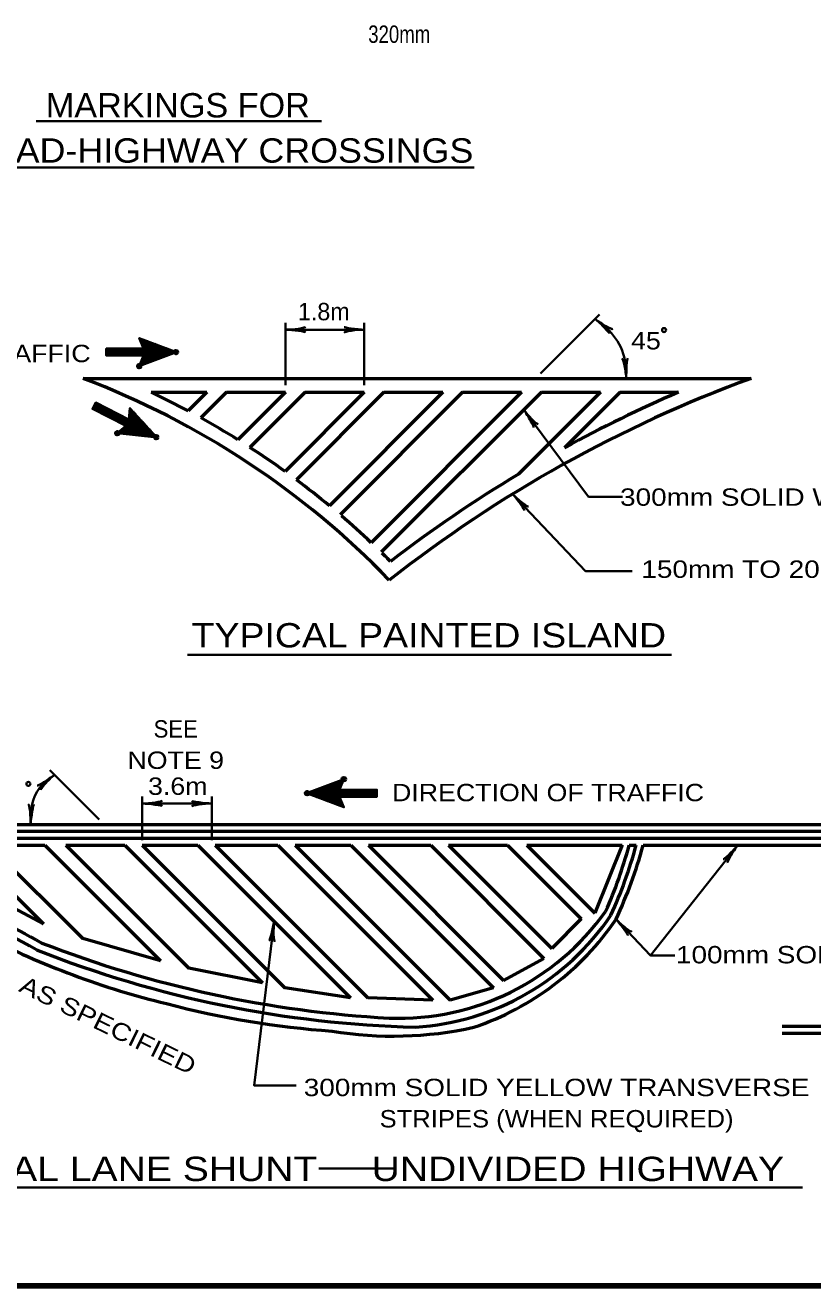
# Model space of a CAD drawing. Extents: x -96 to 617, y -65 to 388.
# Drawn here: x 24.1 to 137.3, y -55.4 to 125.9 of the extents above; entities that cross this region are included whole.
import ezdxf
from ezdxf.enums import TextEntityAlignment as Align

# ---------------------------------------------------------------- set-up
doc = ezdxf.new("R2010")
doc.units = 0
doc.header["$PDMODE"] = 32
doc.header["$PDSIZE"] = 0.5
doc.layers.add('1', color=7, linetype='Continuous', lineweight=53)

msp = doc.modelspace()

# ---------------------------------------------------------------- linework, layer by layer
at = {"layer": '1', "lineweight": 40}
for p, q in [((25.644, 112.056), (66.627, 112.056)), ((3.249, 105.393), (88.592, 105.393)), ((47.366, 35.304), (116.953, 35.304)), ((66.278, -38.548), (77.278, -38.548)), ((3.977, -41.268), (135.772, -41.268))]:
    msp.add_line(p, q, dxfattribs=at)
at = {"layer": '1', "lineweight": 35}
for p, q in [((106.608, 84.265), (98.123, 75.78)), ((61.474, 74.073), (61.474, 83.073)), ((61.474, 82.073), (72.788, 82.073)), ((72.788, 74.073), (72.788, 83.073)), ((40.451, 80.776), (43.387, 77.941)), ((40.552, 80.573), (43.286, 77.839)), ((40.653, 80.776), (43.488, 77.941)), ((40.653, 80.371), (43.185, 77.839)), ((40.755, 80.067), (43.083, 77.839)), ((40.856, 80.674), (43.59, 78.042)), ((40.856, 79.864), (42.982, 77.738)), ((41.058, 80.674), (43.691, 78.042)), ((41.362, 80.573), (43.792, 78.042)), ((41.565, 80.472), (43.893, 78.143)), ((41.767, 80.371), (43.995, 78.143)), ((41.97, 80.269), (44.096, 78.244)), ((42.273, 80.168), (44.197, 78.244)), ((42.476, 80.067), (44.298, 78.244)), ((42.678, 80.067), (44.4, 78.346)), ((42.982, 79.966), (44.501, 78.346)), ((43.185, 79.864), (44.602, 78.447)), ((43.387, 79.763), (44.703, 78.447)), ((35.692, 79.358), (41.058, 79.358)), ((35.692, 79.257), (36.603, 78.346)), ((35.692, 79.156), (36.502, 78.346)), ((35.692, 79.054), (36.401, 78.346)), ((35.692, 78.852), (36.198, 78.346)), ((35.692, 78.751), (36.097, 78.346)), ((35.692, 78.548), (35.895, 78.346)), ((35.692, 78.447), (35.793, 78.346)), ((35.793, 79.358), (36.806, 78.346)), ((35.895, 79.358), (36.907, 78.346)), ((36.097, 79.358), (37.11, 78.346)), ((36.198, 79.358), (37.211, 78.346)), ((36.401, 79.358), (37.413, 78.346)), ((36.502, 79.358), (37.515, 78.346)), ((36.603, 79.358), (37.616, 78.346)), ((36.806, 79.358), (37.818, 78.346)), ((36.907, 79.358), (37.92, 78.346)), ((37.11, 79.358), (38.122, 78.346)), ((37.211, 79.358), (38.223, 78.346)), ((37.312, 79.358), (38.325, 78.346)), ((37.515, 79.358), (38.527, 78.346)), ((37.616, 79.358), (38.628, 78.346)), ((37.818, 79.358), (38.831, 78.346)), ((37.92, 79.358), (38.932, 78.346)), ((38.122, 79.358), (39.135, 78.346)), ((38.223, 79.358), (39.236, 78.346)), ((38.325, 79.358), (39.337, 78.346)), ((38.527, 79.358), (39.54, 78.346)), ((38.628, 79.358), (39.641, 78.346)), ((38.831, 79.358), (39.843, 78.346)), ((38.932, 79.358), (39.945, 78.346)), ((39.033, 79.358), (40.046, 78.346)), ((39.236, 79.358), (40.248, 78.346)), ((39.337, 79.358), (40.35, 78.346)), ((39.54, 79.358), (40.552, 78.346)), ((39.641, 79.358), (40.653, 78.346)), ((39.742, 79.358), (40.755, 78.346)), ((39.945, 79.358), (40.957, 78.346)), ((40.046, 79.358), (41.97, 77.434)), ((40.248, 79.358), (42.172, 77.434)), ((40.35, 79.358), (42.273, 77.536)), ((40.552, 79.358), (42.375, 77.536)), ((40.653, 79.358), (42.476, 77.536)), ((40.755, 79.358), (42.577, 77.637)), ((40.957, 79.662), (42.881, 77.738)), ((40.957, 79.358), (42.678, 77.637)), ((40.957, 78.143), (41.767, 77.333)), ((40.957, 78.042), (41.666, 77.333)), ((41.058, 79.358), (42.78, 77.738)), ((41.058, 78.244), (41.868, 77.333)), ((43.59, 79.662), (44.805, 78.447)), ((43.893, 79.561), (44.906, 78.548)), ((44.096, 79.459), (45.007, 78.548)), ((44.298, 79.459), (45.108, 78.548)), ((44.501, 79.358), (45.21, 78.649)), ((44.805, 79.257), (45.311, 78.649)), ((45.007, 79.156), (45.412, 78.751)), ((45.21, 79.054), (45.513, 78.751)), ((45.412, 78.953), (45.615, 78.751)), ((40.451, 76.928), (40.552, 76.827)), ((40.552, 77.131), (40.755, 76.928)), ((40.552, 77.029), (40.653, 76.928)), ((40.653, 77.434), (41.058, 77.029)), ((40.653, 77.333), (40.957, 77.029)), ((40.653, 77.232), (40.856, 77.029)), ((40.755, 77.637), (41.261, 77.131)), ((40.755, 77.536), (41.16, 77.131)), ((40.856, 77.941), (41.565, 77.232)), ((40.856, 77.839), (41.463, 77.232)), ((40.856, 77.738), (41.362, 77.232)), ((33.771, 70.777), (33.816, 70.641)), ((33.817, 70.868), (33.906, 70.596)), ((33.908, 71.048), (34.087, 70.504)), ((33.954, 71.139), (34.177, 70.459)), ((34.045, 71.319), (34.358, 70.367)), ((34.091, 71.41), (34.448, 70.322)), ((34.136, 71.5), (34.539, 70.276)), ((34.182, 71.59), (38.971, 69.17)), ((34.272, 71.545), (34.719, 70.184)), ((34.363, 71.499), (34.81, 70.139)), ((34.544, 71.408), (34.99, 70.047)), ((34.634, 71.362), (35.081, 70.002)), ((34.815, 71.271), (35.261, 69.91)), ((34.905, 71.225), (35.352, 69.865)), ((34.995, 71.179), (35.442, 69.819)), ((35.176, 71.088), (35.623, 69.728)), ((35.266, 71.042), (35.713, 69.682)), ((35.447, 70.951), (35.894, 69.591)), ((35.538, 70.905), (35.984, 69.545)), ((35.628, 70.86), (36.075, 69.499)), ((35.809, 70.768), (36.255, 69.408)), ((35.899, 70.723), (36.346, 69.362)), ((39.069, 70.709), (40.41, 66.854)), ((36.08, 70.631), (36.527, 69.271)), ((36.17, 70.586), (36.617, 69.225)), ((36.351, 70.494), (36.798, 69.134)), ((36.441, 70.449), (36.888, 69.088)), ((36.532, 70.403), (36.978, 69.043)), ((36.712, 70.312), (37.159, 68.951)), ((36.803, 70.266), (37.249, 68.906)), ((36.983, 70.175), (37.43, 68.814)), ((37.074, 70.129), (37.521, 68.769)), ((37.164, 70.083), (37.611, 68.723)), ((37.345, 69.992), (37.792, 68.632)), ((37.435, 69.946), (37.882, 68.586)), ((37.616, 69.855), (38.063, 68.495)), ((37.706, 69.809), (38.153, 68.449)), ((37.797, 69.764), (38.243, 68.403)), ((37.977, 69.672), (38.424, 68.312)), ((38.068, 69.626), (38.917, 67.042)), ((38.248, 69.535), (39.097, 66.95)), ((38.339, 69.489), (39.233, 66.995)), ((38.52, 69.398), (39.324, 66.95)), ((38.61, 69.352), (39.414, 66.904)), ((38.7, 69.307), (39.55, 66.948)), ((38.881, 69.215), (39.641, 66.903)), ((38.971, 69.17), (39.777, 66.947)), ((39.018, 69.487), (39.867, 66.902)), ((39.019, 69.713), (39.957, 66.856)), ((39.02, 69.939), (40.093, 66.901)), ((39.067, 70.256), (40.184, 66.855)), ((39.068, 70.483), (40.274, 66.809)), ((39.249, 70.618), (40.501, 66.809)), ((39.384, 70.436), (40.637, 66.853)), ((39.565, 70.344), (40.727, 66.808)), ((39.791, 70.117), (40.817, 66.762)), ((39.925, 69.935), (40.953, 66.807)), ((40.061, 69.754), (41.044, 66.761)), ((40.196, 69.572), (41.18, 66.806)), ((40.421, 69.345), (41.27, 66.76)), ((40.556, 69.163), (41.361, 66.714)), ((40.737, 69.072), (41.497, 66.759)), ((37.333, 67.275), (37.378, 67.139)), ((37.469, 67.32), (37.514, 67.184)), ((37.515, 67.41), (37.604, 67.138)), ((37.651, 67.455), (37.74, 67.183)), ((37.696, 67.545), (37.83, 67.137)), ((37.742, 67.636), (37.921, 67.091)), ((37.878, 67.68), (38.057, 67.136)), ((37.924, 67.771), (38.147, 67.09)), ((38.06, 67.815), (38.283, 67.135)), ((38.105, 67.906), (38.374, 67.09)), ((38.151, 67.996), (38.464, 67.044)), ((38.287, 68.041), (38.6, 67.088)), ((38.333, 68.131), (38.69, 67.043)), ((38.469, 68.176), (38.781, 66.997)), ((40.962, 68.844), (41.587, 66.713)), ((41.097, 68.662), (41.723, 66.758)), ((41.232, 68.481), (41.813, 66.712)), ((41.367, 68.299), (41.904, 66.667)), ((41.593, 68.072), (42.04, 66.711)), ((41.728, 67.89), (42.13, 66.666)), ((41.909, 67.799), (42.22, 66.62)), ((42.044, 67.617), (42.356, 66.665)), ((42.269, 67.389), (42.447, 66.619)), ((42.404, 67.208), (42.583, 66.664)), ((42.539, 67.026), (42.673, 66.618)), ((42.674, 66.844), (42.764, 66.572)), ((27.601, 18.721), (34.672, 11.65)), ((69.653, 13.494), (66.818, 16.329)), ((69.855, 13.494), (66.919, 16.329)), ((69.754, 13.696), (67.02, 16.43)), ((69.653, 13.899), (67.122, 16.43)), ((69.552, 14.202), (67.223, 16.43)), ((69.45, 14.405), (67.324, 16.531)), ((69.349, 14.607), (67.425, 16.531)), ((69.248, 14.911), (67.527, 16.531)), ((69.349, 14.911), (67.628, 16.633)), ((69.552, 14.911), (67.729, 16.633)), ((69.653, 14.911), (67.83, 16.734)), ((69.754, 14.911), (67.932, 16.734)), ((69.957, 14.911), (68.033, 16.734)), ((70.058, 14.911), (68.134, 16.835)), ((70.26, 14.911), (68.337, 16.835)), ((69.248, 16.025), (68.438, 16.936)), ((69.349, 16.126), (68.539, 16.936)), ((69.349, 16.227), (68.64, 16.936)), ((69.45, 16.329), (68.742, 17.037)), ((69.45, 16.43), (68.843, 17.037)), ((69.45, 16.531), (68.944, 17.037)), ((69.552, 16.633), (69.045, 17.139)), ((69.552, 16.734), (69.147, 17.139)), ((69.653, 16.835), (69.248, 17.24)), ((69.653, 16.936), (69.349, 17.24)), ((69.653, 17.037), (69.45, 17.24)), ((69.754, 17.139), (69.552, 17.341)), ((69.754, 17.24), (69.653, 17.341)), ((69.855, 17.341), (69.754, 17.442)), ((40.879, 8.692), (40.879, 14.942)), ((50.879, 8.692), (50.879, 14.942)), ((64.894, 15.316), (64.692, 15.519)), ((65.097, 15.215), (64.793, 15.519)), ((65.299, 15.114), (64.894, 15.519)), ((65.502, 15.012), (64.995, 15.62)), ((65.805, 14.911), (65.097, 15.62)), ((66.008, 14.81), (65.198, 15.721)), ((66.21, 14.81), (65.299, 15.721)), ((66.413, 14.709), (65.4, 15.721)), ((66.717, 14.607), (65.502, 15.822)), ((66.919, 14.506), (65.603, 15.822)), ((67.122, 14.405), (65.704, 15.822)), ((67.324, 14.304), (65.805, 15.924)), ((67.628, 14.202), (65.907, 15.924)), ((67.83, 14.202), (66.008, 16.025)), ((68.033, 14.101), (66.109, 16.025)), ((68.337, 14), (66.21, 16.025)), ((68.539, 13.899), (66.312, 16.126)), ((68.742, 13.797), (66.413, 16.126)), ((68.944, 13.696), (66.514, 16.227)), ((69.248, 13.595), (66.615, 16.227)), ((69.45, 13.595), (66.717, 16.227)), ((74.614, 14.911), (69.248, 14.911)), ((70.362, 14.911), (69.349, 15.924)), ((70.564, 14.911), (69.552, 15.924)), ((70.665, 14.911), (69.653, 15.924)), ((70.767, 14.911), (69.754, 15.924)), ((70.969, 14.911), (69.957, 15.924)), ((71.07, 14.911), (70.058, 15.924)), ((71.273, 14.911), (70.26, 15.924)), ((71.374, 14.911), (70.362, 15.924)), ((71.475, 14.911), (70.463, 15.924)), ((71.678, 14.911), (70.665, 15.924)), ((71.779, 14.911), (70.767, 15.924)), ((71.982, 14.911), (70.969, 15.924)), ((72.083, 14.911), (71.07, 15.924)), ((72.184, 14.911), (71.172, 15.924)), ((72.387, 14.911), (71.374, 15.924)), ((72.488, 14.911), (71.475, 15.924)), ((72.69, 14.911), (71.678, 15.924)), ((72.792, 14.911), (71.779, 15.924)), ((72.994, 14.911), (71.982, 15.924)), ((73.095, 14.911), (72.083, 15.924)), ((73.197, 14.911), (72.184, 15.924)), ((73.399, 14.911), (72.387, 15.924)), ((73.5, 14.911), (72.488, 15.924)), ((73.703, 14.911), (72.69, 15.924)), ((73.804, 14.911), (72.792, 15.924)), ((73.905, 14.911), (72.893, 15.924)), ((74.108, 14.911), (73.095, 15.924)), ((74.209, 14.911), (73.197, 15.924)), ((74.412, 14.911), (73.399, 15.924)), ((74.513, 14.911), (73.5, 15.924)), ((74.614, 15.012), (73.703, 15.924)), ((74.614, 15.114), (73.804, 15.924)), ((74.614, 15.215), (73.905, 15.924)), ((74.614, 15.417), (74.108, 15.924)), ((74.614, 15.519), (74.209, 15.924)), ((74.614, 15.721), (74.412, 15.924)), ((74.614, 15.822), (74.513, 15.924)), ((40.879, 13.942), (50.879, 13.942)), ((113.925, -7.9), (117.444, -7.9))]:
    msp.add_line(p, q, dxfattribs=at)
at = {"layer": '1'}
for p, q in [((32.387, 75.073), (128.387, 75.073)), ((42.161, 73.073), (50.161, 73.073)), ((50.161, 73.073), (47.476, 70.388)), ((52.989, 73.073), (49.305, 69.388)), ((52.989, 73.073), (61.474, 73.073)), ((61.474, 73.073), (54.637, 66.235)), ((64.303, 73.073), (56.364, 65.134)), ((72.788, 73.073), (61.4, 61.685)), ((75.617, 73.073), (63.031, 60.487)), ((64.303, 73.073), (72.788, 73.073)), ((84.102, 73.073), (67.781, 56.752)), ((86.93, 73.073), (69.318, 55.46)), ((95.415, 73.073), (73.79, 51.447)), ((98.244, 73.073), (75.234, 50.063)), ((75.617, 73.073), (84.102, 73.073)), ((86.93, 73.073), (95.415, 73.073)), ((106.729, 73.073), (94.943, 61.286)), ((98.244, 73.073), (106.729, 73.073)), ((109.558, 73.073), (101.578, 65.093)), ((109.558, 73.073), (117.952, 73.073)), ((-19.121, 10.942), (168.879, 10.942)), ((-19.121, 9.942), (168.879, 9.942)), ((-19.121, 8.942), (168.879, 8.942)), ((5.379, 7.942), (26.693, -3.371)), ((15.379, 7.942), (26.693, -3.371)), ((18.879, 7.942), (26.879, 7.942)), ((18.879, 7.942), (32.314, -5.492)), ((26.879, 7.942), (43.496, -8.675)), ((29.879, 7.942), (38.379, 7.942)), ((29.879, 7.942), (47.557, -9.735)), ((38.379, 7.942), (58.178, -11.857)), ((40.879, 7.942), (48.879, 7.942)), ((40.879, 7.942), (61.386, -12.564)), ((48.879, 7.942), (70.8, -13.978)), ((51.379, 7.942), (60.379, 7.942)), ((51.379, 7.942), (73.3, -13.978)), ((60.379, 7.942), (82.653, -14.331)), ((62.879, 7.942), (70.879, 7.942)), ((62.879, 7.942), (85.153, -14.331)), ((70.879, 7.942), (91.385, -12.564)), ((73.379, 7.942), (82.346, 7.942)), ((73.379, 7.942), (92.825, -11.503)), ((82.346, 7.942), (98.621, -8.333)), ((84.879, 7.942), (93.379, 7.942)), ((84.879, 7.942), (99.729, -6.907)), ((93.379, 7.942), (103.986, -2.664)), ((96.171, 7.942), (109.879, 7.942)), ((96.171, 7.942), (105.922, -1.809)), ((109.879, 7.942), (105.922, -1.809)), ((110.879, 7.942), (111.879, 7.942)), ((112.879, 7.942), (168.879, 7.942)), ((103.986, -2.664), (99.729, -6.907)), ((43.496, -8.675), (32.314, -5.492)), ((98.621, -8.333), (92.825, -11.503)), ((58.178, -11.857), (47.557, -9.735)), ((70.8, -13.978), (61.386, -12.564)), ((91.385, -12.564), (85.153, -14.331)), ((82.653, -14.331), (73.3, -13.978)), ((132.879, -18.058), (168.879, -18.058)), ((132.879, -19.058), (168.879, -19.058))]:
    msp.add_line(p, q, dxfattribs=at)
at = {"layer": '1', "lineweight": 158}
msp.add_line((611.853, -55.407), (-47.814, -55.407), dxfattribs=at)
at = {"layer": '1', "lineweight": 35}
for points in [[(45.817, 78.852), (40.451, 76.827), (41.058, 78.346), (35.692, 78.346), (35.692, 79.358), (41.058, 79.358), (40.451, 80.877)], [(42.99, 66.571), (37.287, 67.185), (38.515, 68.266), (33.725, 70.687), (34.182, 71.59), (38.971, 69.17), (39.114, 70.799)], [(64.489, 15.417), (69.855, 17.442), (69.248, 15.924), (74.614, 15.924), (74.614, 14.911), (69.248, 14.911), (69.855, 13.393)]]:
    msp.add_lwpolyline(points, close=True, dxfattribs=at)
for points in [[(41.058, 78.346), (35.692, 78.346), (35.692, 79.358)], [(38.515, 68.266), (33.725, 70.687), (34.182, 71.59)], [(95.729, 70.558), (105.036, 58.043), (109.919, 58.043)], [(94.114, 58.441), (104.578, 47.357), (111.292, 47.357)], [(69.248, 15.924), (74.614, 15.924), (74.614, 14.911)], [(108.976, -2.701), (113.925, -7.9), (126.479, 7.942)], [(59.84, -3.018), (56.988, -26.628), (62.994, -26.628)]]:
    msp.add_lwpolyline(points, dxfattribs=at)
for centre in [(115.88, 82.02), (24.512, 16.767)]:
    msp.add_circle(centre, 0.285, dxfattribs=at)
for centre, radius, start, end in [((101.928, 76.012), 8.487, 1.18439, 54.5209), ((30.985, 12.476), 6.103, 128.36921, 182.32109)]:
    msp.add_arc(centre, radius, start, end, dxfattribs=at)
at = {"layer": '1'}
for centre, radius, start, end in [((-10.692, -38.168), 121.158, 44.05079, 69.17219), ((193.744, -103.239), 189.911, 110.12936, 128.16678), ((-10.692, -38.168), 123.158, 61.81611, 64.5867), ((193.744, -103.239), 191.911, 113.26155, 118.70186), ((-10.692, -38.168), 123.158, 57.9643, 60.84654), ((-10.692, -38.168), 123.158, 54.1713, 57.0113), ((-10.692, -38.168), 123.158, 50.41849, 53.23002), ((193.744, -103.239), 191.911, 120.98582, 127.63172), ((-10.692, -38.168), 123.158, 46.68889, 49.36196), ((-10.692, -38.168), 123.158, 44.88702, 45.6763), ((-80.833, -196.113), 216.961, 60.60058, 70.13846), ((2132.222, 3850.287), 4393.885, 240.98294, 241.36318), ((47.173, 25.266), 66.02, 336.00198, 344.78774), ((48.173, 25.266), 66.02, 335.49783, 344.78774), ((49.173, 25.266), 66.02, 334.93685, 344.78774), ((77.674, 19.687), 36.623, 267.94833, 324.49156), ((77.89, 18.289), 36.577, 273.54625, 326.09486), ((75.823, 19.71), 40.018, 288.52428, 325.94269), ((72.425, 100.59), 118.784, 242.78447, 256.33579), ((84.143, 140.277), 158.545, 248.35865, 268.5577), ((85.493, 146.221), 163.389, 248.80685, 266.7966), ((76.888, 107.643), 126.72, 255.1283, 266.05296), ((76.96, 33.825), 53.332, 260.50912, 282.53719)]:
    msp.add_arc(centre, radius, start, end, dxfattribs=at)
at = {"layer": '1', "lineweight": 40}
for centre, major_axis, ratio, start_param, end_param in [((106.727, 82.762), (-1.271, 1.225), 0.07063, 3.1407148, 5.41811), ((107.006, 83.164), (-1.499, 0.983), 0.122415, 0.8963533, 3.1415927), ((62.595, 81.861), (-1.756, 0.176), 0.07063, 3.1407148, 5.41811), ((62.595, 81.861), (-1.756, 0.176), 0.07063, 3.1407148, 5.41811), ((62.566, 82.349), (-1.786, -0.156), 0.122415, 0.8963533, 3.1415927), ((62.566, 82.349), (-1.786, -0.156), 0.122415, 0.8963533, 3.1415927), ((71.697, 81.796), (1.786, 0.156), 0.122415, 0.8963533, 3.1415927), ((71.668, 82.284), (1.756, -0.176), 0.07063, 3.1407148, 5.41811), ((110.593, 76.201), (-0.061, -1.764), 0.07063, 3.1407148, 5.41811), ((110.108, 76.14), (0.272, -1.772), 0.122415, 0.8963533, 3.1415927), ((96.228, 69.532), (-0.907, 1.514), 0.07063, 3.1407148, 5.41811), ((96.228, 69.532), (-0.907, 1.514), 0.07063, 3.1407148, 5.41811), ((96.602, 69.847), (-1.191, 1.34), 0.122415, 0.8963533, 3.1415927), ((96.602, 69.847), (-1.191, 1.34), 0.122415, 0.8963533, 3.1415927), ((94.729, 57.481), (-1.078, 1.398), 0.07063, 3.1407148, 5.41811), ((95.064, 57.837), (-1.339, 1.191), 0.122415, 0.8963533, 3.1415927), ((27.253, 17.503), (-1.463, -0.987), 0.07063, 6.2823074, 8.5597026), ((27.587, 17.146), (1.274, 1.261), 0.122415, 0.8963533, 3.1415927), ((24.588, 12.043), (0.09, -1.79), 0.122415, 0.8963533, 3.1415927), ((25.077, 12.054), (0.24, 1.749), 0.07063, 6.2823074, 8.5597026), ((42, 13.731), (-1.756, 0.176), 0.07063, 3.1407148, 5.41811), ((41.971, 14.219), (-1.786, -0.156), 0.122415, 0.8963533, 3.1415927), ((49.788, 13.666), (1.786, 0.156), 0.122415, 0.8963533, 3.1415927), ((49.759, 14.154), (1.756, -0.176), 0.07063, 3.1407148, 5.41811), ((125.618, 7.196), (1.229, 1.268), 0.07063, 3.1407148, 5.41811), ((126.018, 6.916), (0.987, 1.497), 0.122415, 0.8963533, 3.1415927), ((59.495, -4.105), (0.385, 1.723), 0.07063, 3.1407148, 5.41811), ((59.495, -4.105), (0.385, 1.723), 0.07063, 3.1407148, 5.41811), ((59.983, -4.134), (0.059, 1.792), 0.122415, 0.8963533, 3.1415927), ((59.983, -4.134), (0.059, 1.792), 0.122415, 0.8963533, 3.1415927), ((109.596, -3.659), (-1.084, 1.393), 0.07063, 3.1407148, 5.41811), ((109.596, -3.659), (-1.084, 1.393), 0.07063, 3.1407148, 5.41811), ((109.929, -3.301), (-1.344, 1.186), 0.122415, 0.8963533, 3.1415927), ((109.929, -3.301), (-1.344, 1.186), 0.122415, 0.8963533, 3.1415927)]:
    msp.add_ellipse(centre, major_axis=major_axis, ratio=ratio, start_param=start_param, end_param=end_param, dxfattribs=at)
at = {"layer": '1'}
for p in [(45.716, 78.852), (40.451, 76.827), (37.287, 67.185), (42.9, 66.617), (69.855, 17.442), (64.59, 15.417)]:
    msp.add_point(p, dxfattribs=at)

# ---------------------------------------------------------------- texts
at = {"layer": '1', "width": 0.8}
msp.add_text('320mm', height=2.5, dxfattribs=at).set_placement((73.355, 123.318))
at = {"layer": '1'}
for s, height, width, p in [('MARKINGS FOR', 3.5, 1.05, (45.994, 112.591)), ('RAILROAD-HIGHWAY CROSSINGS', 3.5, 1.1, (45.994, 106.091)), ('45', 2.5, 1.15, (113.276, 79.234)), ('DIRECTION OF MAINLINE TRAFFIC', 2.5, 1.15, (1.415, 77.402)), ('300mm SOLID WHITE TRANSVERSE STRIPES', 2.5, 1.2, (153.139, 56.752)), ('150mm TO 200mm SOLID WHITE CHANNELIZING LINE', 2.5, 1.2, (164.003, 46.387)), ('TYPICAL PAINTED ISLAND', 3.5, 1.15, (82.074, 36.384)), ('SEE', 2.5, 0.95, (45.689, 23.418)), ('NOTE 9', 2.5, 1.15, (45.689, 18.918)), ('3.6m', 2.5, 1.15, (45.985, 15.186)), ('DIRECTION OF TRAFFIC', 2.5, 1.15, (99.204, 14.268)), ('100mm SOLID DOUBLE YELLOW BARRIER LINES', 2.5, 1.2, (164.415, -9.047)), ('300mm SOLID YELLOW TRANSVERSE', 2.5, 1.2, (100.433, -28.137)), ('STRIPES (WHEN REQUIRED)', 2.5, 1.1, (100.433, -32.637)), ('TYPICAL LANE SHUNT     UNDIVIDED HIGHWAY', 3.5, 1.2, (69.318, -40.346))]:
    msp.add_text(s, height=height, dxfattribs=dict(at, width=width)).set_placement(p, align=Align.CENTER)
msp.add_text('1.8m', height=2.5, dxfattribs=at).set_placement((66.974, 83.427), align=Align.CENTER)
at = {"layer": '1', "width": 1.2}
msp.add_text('TAPER L OR AS SPECIFIED', height=2.5, rotation=333.998, dxfattribs=at).set_placement((24.173, -13.593), align=Align.CENTER)

doc.saveas('drawing.dxf')
